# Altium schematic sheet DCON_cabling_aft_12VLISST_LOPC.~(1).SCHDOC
size B; Organization: Monterey Bay Aquarium Research Institute; Address1: 7700 Sandholdt Rd; Address2: Moss Landing, CA 95039-9644; CompanyName: MBARI
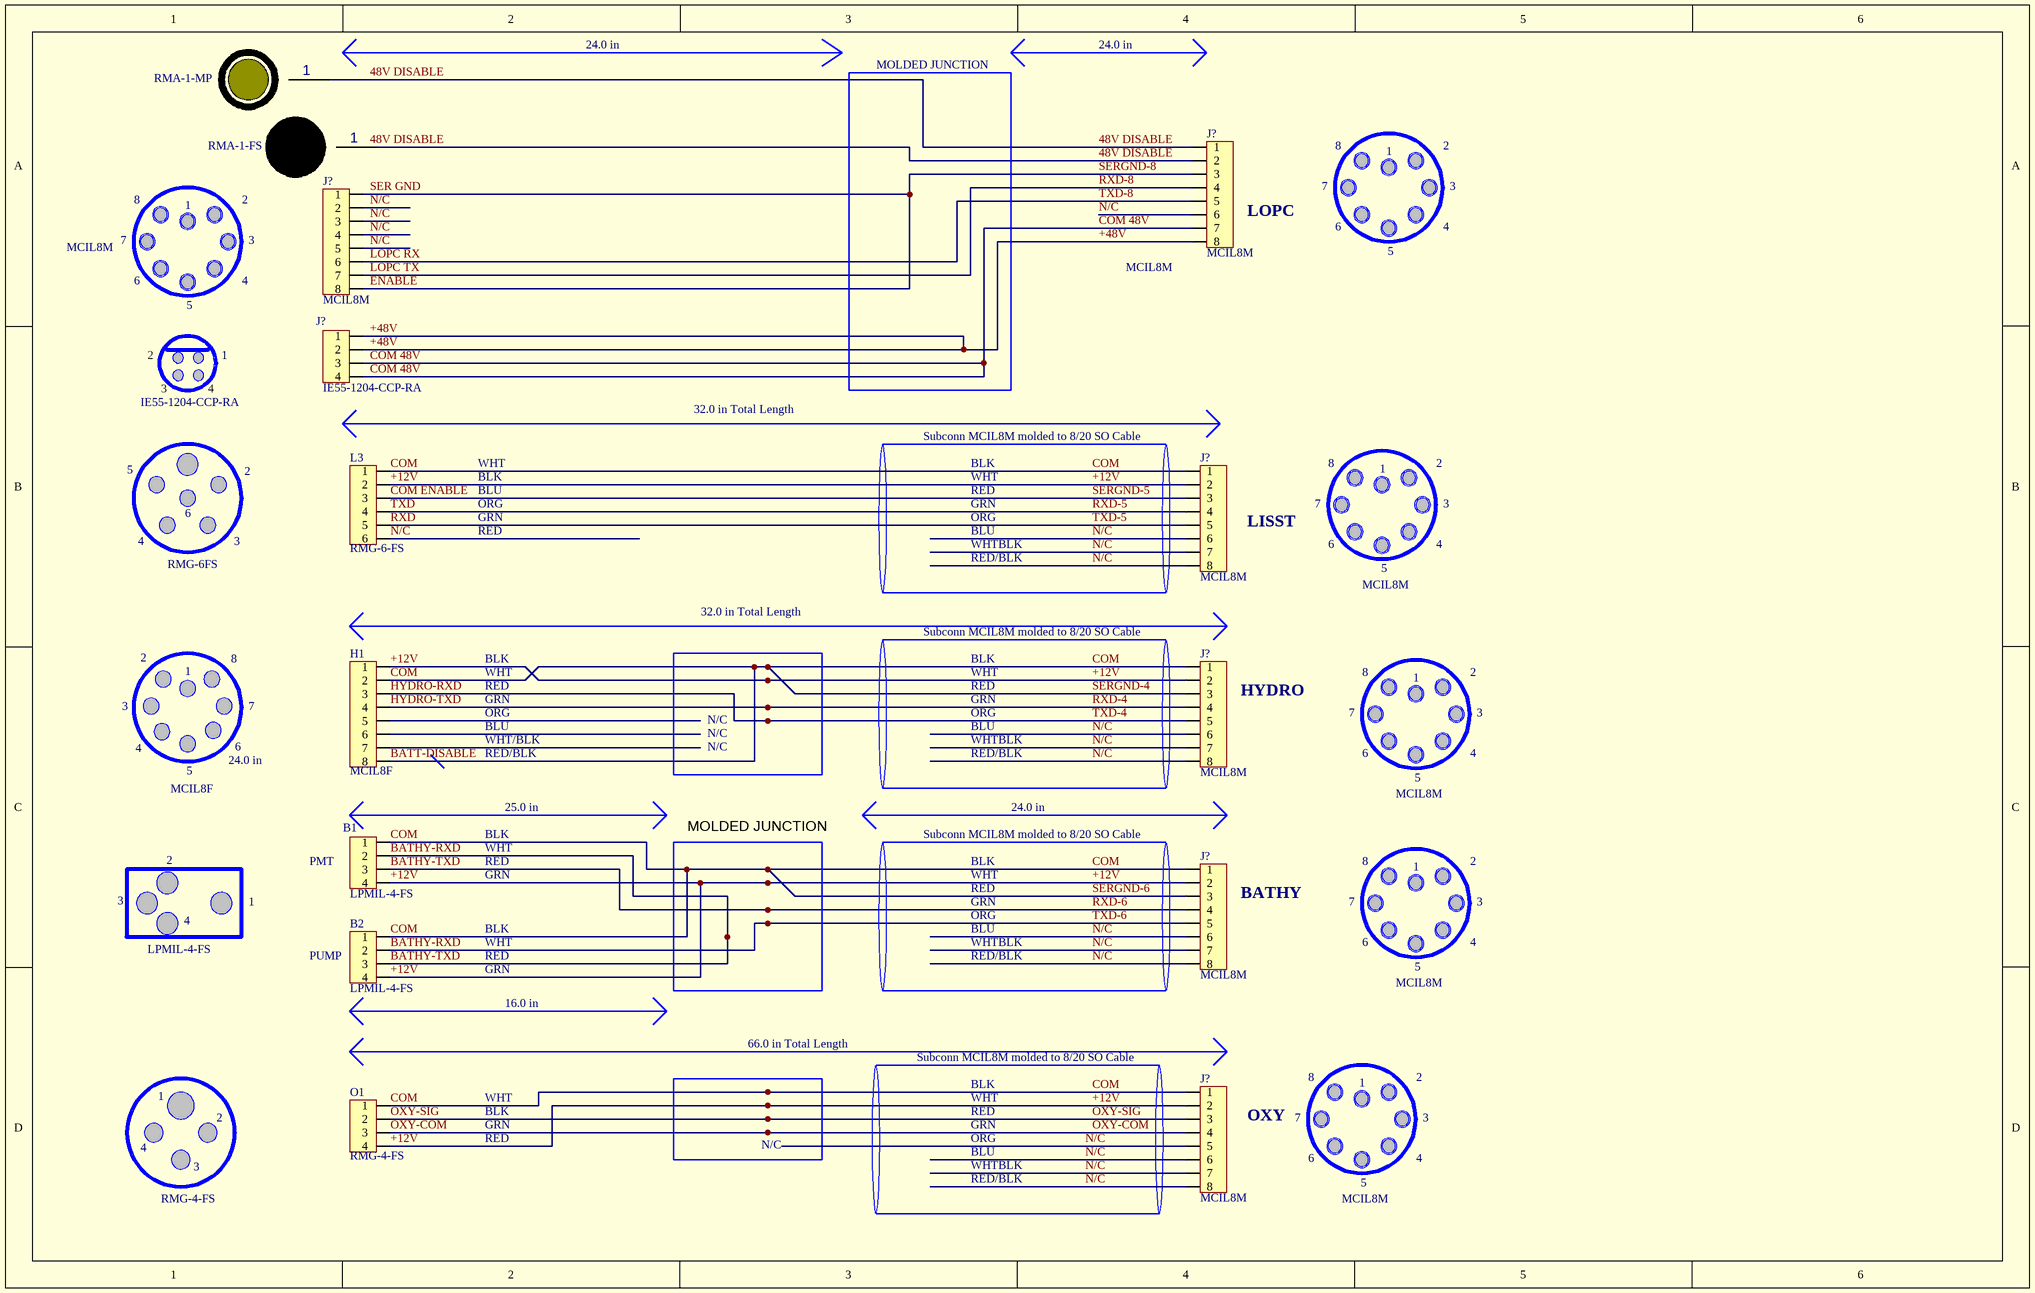
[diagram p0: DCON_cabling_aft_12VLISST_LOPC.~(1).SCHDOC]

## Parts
(Parts that share a designator on the sheet are numbered #1, #2 ... from top to bottom, then left to right.)
*#1  RMA-1-MP  [None Available]
*#2  RMA-1-FS  [None Available]
B1  LPMIL-4-FS  [SIP4]
B2  LPMIL-4-FS  [SIP4]
H1  MCIL8F  [SIP6]
J?#1  MCIL8M  [SIP8]
J?#2  MCIL8M  [SIP8]
J?#3  IE55-1204-CCP-RA  [SIP4]
J?#4  MCIL8M  [SIP8]
J?#5  MCIL8M  [SIP8]
J?#6  MCIL8M  [SIP8]
J?#7  MCIL8M  [SIP8]
L3  RMG-6-FS  [SIP6]
O1  RMG-4-FS  [SIP6]

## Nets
48V DISABLE: *#1.1 *#2.1 J?#1.1 J?#1.2
+12V: B1.4 B2.4 H1.1 J?#4.2 J?#5.2 J?#6.2 J?#7.2 L3.2 O1.4
+48V: J?#1.8 J?#3.1 J?#3.2
BATHY-RXD: B1.2 B1.3 B2.2 B2.3 J?#6.4 J?#6.5  [also labelled BATHY-TXD, RXD-6, TXD-6]
BATT-DISABLE: B1.1 B2.1 H1.2 H1.8 J?#4.1 J?#5.1 J?#5.3 J?#6.1 J?#6.3 J?#7.1 L3.1 O1.1  [also labelled COM, SERGND-4, SERGND-6]
COM 48V: J?#1.7 J?#3.3 J?#3.4
COM ENABLE: J?#4.3 L3.3  [also labelled SERGND-5]
HYDRO-RXD: H1.3 J?#5.5  [also labelled TXD-4]
HYDRO-TXD: H1.4 J?#5.4  [also labelled RXD-4]
N/C: J?#1.6 J?#2.2 J?#2.3 J?#2.4 J?#2.5 J?#4.6 J?#4.7 J?#4.8 J?#5.6 J?#5.7 J?#5.8 J?#6.6 J?#6.7 J?#6.8 J?#7.5 J?#7.6 J?#7.7 J?#7.8 L3.6
OXY-COM: J?#7.4 O1.3
OXY-SIG: J?#7.3 O1.2
RXD: J?#4.5 L3.5  [also labelled TXD-5]
RXD-5: J?#4.4 L3.4  [also labelled TXD]
RXD-8: J?#1.4 J?#2.7
SERGND-8: J?#1.3 J?#2.1 J?#2.8
TXD-8: J?#1.5 J?#2.6

Not connected (* = marked no-connect by the designer): H1 5 6 7

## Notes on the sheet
- 48V DISABLE
- 24.0 in
- MOLDED JUNCTION
- 8
- 1
- 2
- (near J?#2) SER GND
- (near J?#1) LOPC
- 7
- 6
- 4
- 3
- MCIL8M
- (near J?#2) LOPC RX
- (near J?#2) LOPC TX
- (near J?#2) ENABLE
- (near J?#1) MCIL8M
- 5
- (near J?#3) +48V
- (near J?#3) COM 48V
- IE55-1204-CCP-RA
- 32.0 in Total Length
- WHT
- BLK
- BLU
- ORG
- (near J?#4) Subconn MCIL8M molded to 8/20 SO Cable
- RED
- GRN
- RMG-6FS
- RED/BLK
- WHTBLK
- (near J?#4) LISST
- (near J?#5) Subconn MCIL8M molded to 8/20 SO Cable
- (near J?#5) HYDRO
- WHT/BLK
- N/C
- MCIL8F
- 25.0 in
- (near J?#6) Subconn MCIL8M molded to 8/20 SO Cable
- (near B1) PMT
- (near J?#6) BATHY
- LPMIL-4-FS
- (near B2) PUMP
- 16.0 in
- 66.0 in Total Length
- Subconn MCIL8M molded to 8/20 SO Cable
- (near J?#7) OXY
- RMG-4-FS

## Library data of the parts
*#1 = RMA1MP: Impulse RMA-1-MP pigtail
*#2 = RMA1FS: Impulse RMA-1-FS pigtail
B1 B2 J?#3 O1 = CON4: Connector
H1 = CON8: Connector
J?#1 J?#2 J?#4-J?#7 = CON8: Connector; ManufPartNo: MCIL8M molded to 24"  8/20 SO Cable; Manufacturer: Subconn
L3 = CON6: Connector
